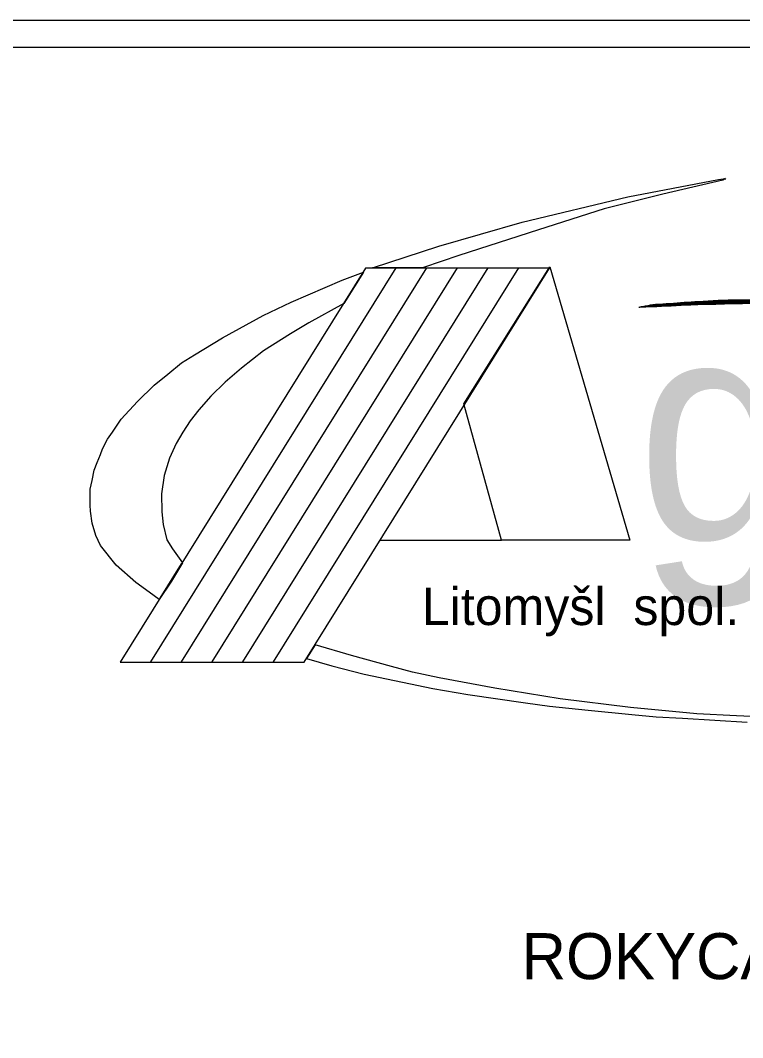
# Model space of a CAD drawing. Extents: x -706631 to -706106, y -1036183 to -1035074.
# Drawn here: x -706141.12 to -706129.35, y -1035972.1 to -1035955.52 of the extents above; entities that cross this region are included whole.
import ezdxf

# ---------------------------------------------------------------- set-up
doc = ezdxf.new("R2010")
doc.units = 0
doc.layers.add('Vrstva 54', color=7, linetype='Continuous')

msp = doc.modelspace()

# ---------------------------------------------------------------- linework, layer by layer
at = {"layer": 'Vrstva 54'}
for p, q in [((-706129.639, -1035958.106), (-706129.634, -1035958.106)), ((-706129.617, -1035958.101), (-706129.616, -1035958.101)), ((-706138.995, -1035965.973), (-706134.998, -1035959.555)), ((-706138.499, -1035965.973), (-706134.499, -1035959.555)), ((-706137.996, -1035965.973), (-706133.999, -1035959.555)), ((-706137.497, -1035965.973), (-706133.5, -1035959.555)), ((-706137.497, -1035965.973), (-706133.5, -1035959.555)), ((-706136.997, -1035965.973), (-706133, -1035959.555)), ((-706130.657, -1035960.139), (-706129.649, -1035960.139)), ((-706130.6, -1035960.135), (-706129.502, -1035960.135)), ((-706130.541, -1035960.132), (-706129.356, -1035960.132)), ((-706130.483, -1035960.128), (-706129.075, -1035960.128)), ((-706130.424, -1035960.123), (-706128.656, -1035960.123)), ((-706130.366, -1035960.12), (-706124.623, -1035960.12)), ((-706130.308, -1035960.114), (-706124.681, -1035960.114)), ((-706130.25, -1035960.112), (-706124.739, -1035960.112)), ((-706130.191, -1035960.107), (-706124.799, -1035960.107)), ((-706130.132, -1035960.101), (-706124.858, -1035960.101)), ((-706130.075, -1035960.099), (-706124.915, -1035960.099)), ((-706129.996, -1035960.095), (-706124.996, -1035960.095)), ((-706129.914, -1035960.092), (-706125.076, -1035960.092)), ((-706129.835, -1035960.086), (-706125.157, -1035960.086)), ((-706129.753, -1035960.082), (-706125.237, -1035960.082)), ((-706129.592, -1035960.075), (-706125.397, -1035960.075)), ((-706131.048, -1035960.196), (-706131.027, -1035960.196)), ((-706131.027, -1035960.19), (-706130.932, -1035960.19)), ((-706131.006, -1035960.185), (-706130.838, -1035960.185)), ((-706130.986, -1035960.183), (-706130.754, -1035960.183)), ((-706130.965, -1035960.178), (-706130.674, -1035960.178)), ((-706130.944, -1035960.174), (-706130.595, -1035960.174)), ((-706130.923, -1035960.17), (-706130.517, -1035960.17)), ((-706130.902, -1035960.166), (-706130.437, -1035960.166)), ((-706130.88, -1035960.162), (-706130.357, -1035960.162)), ((-706130.86, -1035960.158), (-706130.278, -1035960.158)), ((-706130.838, -1035960.153), (-706130.199, -1035960.153)), ((-706130.818, -1035960.151), (-706130.086, -1035960.151)), ((-706130.774, -1035960.146), (-706129.941, -1035960.146)), ((-706130.715, -1035960.144), (-706129.794, -1035960.144)), ((-706135.264, -1035963.99), (-706133.281, -1035963.99)), ((-706138.847, -1035964.936), (-706138.499, -1035964.375))]:
    msp.add_line(p, q, dxfattribs=at)
for points in [[(-706200.491, -1035955.52), (-706112.991, -1035955.52), (-706112.991, -1035995.52), (-706200.491, -1035995.52)], [(-706199.89, -1035955.96), (-706113.39, -1035955.96), (-706113.39, -1035994.96), (-706199.89, -1035994.96)], [(-706135.384, -1035959.555), (-706134.305, -1035959.199), (-706132.946, -1035958.809), (-706131.225, -1035958.398), (-706129.75, -1035958.111), (-706129.633, -1035958.097), (-706129.675, -1035958.125), (-706130.653, -1035958.35), (-706131.611, -1035958.591), (-706132.681, -1035958.931), (-706133.98, -1035959.354), (-706134.556, -1035959.549)], [(-706138.86, -1035964.955), (-706139.022, -1035964.836), (-706139.242, -1035964.682), (-706139.56, -1035964.398), (-706139.816, -1035964.076), (-706139.891, -1035963.914), (-706139.953, -1035963.711), (-706139.981, -1035963.517), (-706139.988, -1035963.42), (-706139.988, -1035963.274), (-706139.984, -1035963.159), (-706139.953, -1035963.02), (-706139.922, -1035962.847), (-706139.874, -1035962.725), (-706139.819, -1035962.595), (-706139.784, -1035962.5), (-706139.705, -1035962.346), (-706139.623, -1035962.231), (-706139.478, -1035962.02), (-706139.215, -1035961.73), (-706138.94, -1035961.465), (-706138.719, -1035961.283), (-706138.496, -1035961.103), (-706138.287, -1035960.97), (-706137.828, -1035960.692), (-706137.168, -1035960.329), (-706136.712, -1035960.111), (-706135.88, -1035959.756), (-706135.534, -1035959.623), (-706135.852, -1035960.136), (-706136.422, -1035960.449), (-706136.724, -1035960.627), (-706137.16, -1035960.907), (-706137.522, -1035961.19), (-706137.785, -1035961.417), (-706138.017, -1035961.643), (-706138.217, -1035961.865), (-706138.358, -1035962.046), (-706138.477, -1035962.228), (-706138.583, -1035962.415), (-706138.692, -1035962.654), (-706138.779, -1035962.936), (-706138.825, -1035963.234), (-706138.818, -1035963.529), (-706138.794, -1035963.736), (-706138.735, -1035963.982), (-706138.645, -1035964.133), (-706138.48, -1035964.361), (-706138.661, -1035964.659)], [(-706132.495, -1035959.536), (-706131.192, -1035963.988), (-706133.281, -1035963.99), (-706133.898, -1035961.77)]]:
    msp.add_lwpolyline(points, close=True, dxfattribs=at)
for points in [[(-706139.498, -1035965.978), (-706136.498, -1035965.978), (-706132.501, -1035959.559), (-706135.499, -1035959.559), (-706139.498, -1035965.978)], [(-706138.499, -1035964.375), (-706138.503, -1035964.369)], [(-706138.852, -1035964.931), (-706138.847, -1035964.936)], [(-706128.631, -1035966.891), (-706129.456, -1035966.852), (-706130.099, -1035966.817), (-706131.182, -1035966.716), (-706132.328, -1035966.573), (-706133.393, -1035966.401), (-706134.297, -1035966.233), (-706134.734, -1035966.141), (-706135.076, -1035966.047), (-706135.729, -1035965.867), (-706136.321, -1035965.698), (-706136.463, -1035965.92), (-706136.048, -1035966.036), (-706135.519, -1035966.173), (-706134.403, -1035966.405), (-706133.832, -1035966.504), (-706132.894, -1035966.643), (-706132.502, -1035966.693), (-706131.874, -1035966.762), (-706131.162, -1035966.829), (-706130.763, -1035966.866), (-706130.335, -1035966.892), (-706129.28, -1035966.957)]]:
    msp.add_lwpolyline(points, dxfattribs=at)

# ---------------------------------------------------------------- texts
for s, height, p in [('groprojekce', 3.60691, (-706131.08, -1035963.996)), ('Litomyšl  spol. s.r.o.', 0.61041, (-706134.582, -1035965.373)), (' ROKYCANOVA 114/IV', 0.75, (-706133.235, -1035971.143))]:
    msp.add_text(s, height=height, rotation=0, dxfattribs=at).set_placement(p)

doc.saveas('drawing.dxf')
